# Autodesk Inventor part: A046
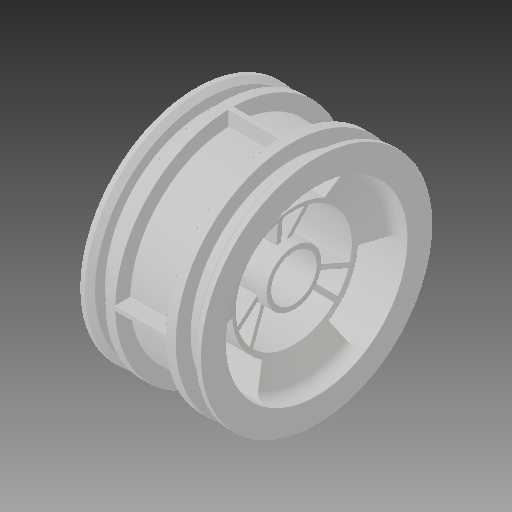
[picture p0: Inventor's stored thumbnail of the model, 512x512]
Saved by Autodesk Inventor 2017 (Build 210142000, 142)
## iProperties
Part Number: A046
Material: Générique
Document SubType Name: Modeling
Designer: ficho
Density: 1 g/cm^3
Appearance: Par défaut
Author: ficho
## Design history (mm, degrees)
feature "Solid1"
node "Solide1"
